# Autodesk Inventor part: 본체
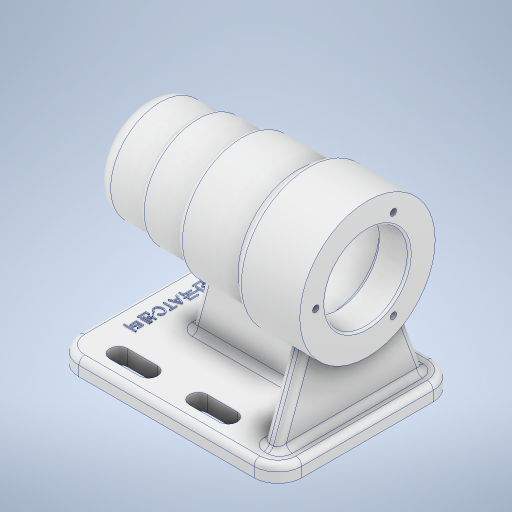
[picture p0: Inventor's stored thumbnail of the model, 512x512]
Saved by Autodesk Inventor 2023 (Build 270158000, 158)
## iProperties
Created: 2022-07
Part Number: 본체
Material: 알루미늄 6061
Document SubType Name: Modeling
Designer: owner
Density: 2.7 g/cm^3
Appearance: 알루미늄 - 평지
Mass: 695.124 g
Surface Area: 704.983 cm^2
Volume: 257.453 cm^3
Author: owner
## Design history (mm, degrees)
sketch "스케치1"
  geometry: L1 (44, -45)-(-44, -45); L2 (-56, -33)-(-56, 33); L3 (-44, 45)-(44, 45); L4 (56, 33)-(56, -33); L5 (56, -45)-(-56, 45); L6 (-56, -45)-(56, 45); A1 r 12 centre (44, -33) between (44, -45) and (56, -33); A2 r 12 centre (44, 33) between (56, 33) and (44, 45); A3 r 12 centre (-44, 33) between (-44, 45) and (-56, 33); A4 r 12 centre (-44, -33) between (-56, -33) and (-44, -45); 1 further point
  constraints: 12 end point, 8 point on circle, 8 point on line, 8 tangent, 4 centre point, 3 equal radius, 2 midpoint, 2 parallel, 1 horizontal, 1 perpendicular
  dimensions: "d0" = 112 distance of L5.end L6.end; "d1" = 90 distance of L6.start L5.end; "d2" = 12 radius of A1
extrude "돌출1" new body sketch "스케치1" distance "d3" = 8; taper "d4" = 0 deg
sketch "스케치2"
  geometry: L1 (-36, 33)-(-21, 33); L2 (-36, 28.5)-(-21, 28.5); L3 (-21, 37.5)-(-36, 37.5); L4 (4, 33)-(19, 33); L5 (4, 28.5)-(19, 28.5); L6 (19, 37.5)-(4, 37.5); L7 (56, -33)-(56, 33) reference; L8 (-56, 33)-(-56, -33) reference; L9 (-56, 33)-(-56, -33) reference; L10 (-56, 0)-(56, 0); L11 (-21, -37.5)-(-36, -37.5); L12 (-36, -28.5)-(-21, -28.5); L13 (19, -37.5)-(4, -37.5); L14 (4, -28.5)-(19, -28.5); A1 r 4.5 centre (-36, 33) between (-36, 37.5) and (-36, 28.5); A2 r 4.5 centre (-21, 33) between (-21, 28.5) and (-21, 37.5); A3 r 4.5 centre (4, 33) between (4, 37.5) and (4, 28.5); A4 r 4.5 centre (19, 33) between (19, 28.5) and (19, 37.5); A5 r 4.5 centre (-21, -33) between (-21, -37.5) and (-21, -28.5); A6 r 4.5 centre (-36, -33) between (-36, -28.5) and (-36, -37.5); A7 r 4.5 centre (4, -33) between (4, -28.5) and (4, -37.5); A8 r 4.5 centre (19, -33) between (19, -37.5) and (19, -28.5); 3 further points
  constraints: 26 end point, 16 point on circle, 12 symmetric about line, 8 centre point, 8 tangent, 4 midpoint, 2 horizontal, 2 parallel, 4 other
  dimensions: "d5" = 15 distance of L1.start L1.end; "d6" = 9 diameter of A2; "d7" = 15 distance of L4.start L4.end; "d8" = 9 diameter of A4; "d10" = 33 vertical distance of point (0, 0) point (-28.5, 33); "d11" = 33 vertical distance of point (0, 0) point (11.5, 33); "d12" = 25 distance of L4.start L1.end; "d13" = 20 distance from line of L8 L1.start
extrude "돌출2" cut sketch "스케치2" extent not by distance; stored distance "d14" = 0; taper "d15" = 0 deg
sketch "스케치3"
  geometry: L1 (-56, 70)-(56, 70); L2 (-44, 0)-(44, 0) reference; L3 (56, 70)-(56, 104); L4 (56, 104)-(24, 104); L5 (24, 104)-(24, 100); L6 (24, 100)-(-10, 100); L7 (-10, 100)-(-10, 97); L8 (-10, 97)-(-32, 97); L9 (-32, 97)-(-32, 95); L10 (-32, 95)-(-56, 95); L11 (-56, 95)-(-56, 70); L12 (56, 91)-(41, 91); L13 (41, 91)-(41, 91); L14 (38, 94)-(-10, 94); L15 (-13, 91)-(-13, 91); L16 (-13, 91)-(-24.7, 91); L17 (-25, 90.7)-(-25, 87.5); L18 (-25, 87.5)-(-42.7, 87.5); L19 (-43, 87.2)-(-43, 86); L20 (-43, 86)-(-46.7, 86); L21 (-47, 85.7)-(-47, 80.5); L22 (-47, 80.5)-(-47, 80.5); L23 (-50, 77.5)-(-50, 70); A1 r 3 centre (-47, 77.5) between (-47, 80.5) and (-50, 77.5); A2 r 0.3 centre (-46.7, 85.7) between (-46.7, 86) and (-47, 85.7); A3 r 0.3 centre (-42.7, 87.2) between (-42.7, 87.5) and (-43, 87.2); A4 r 3 centre (-10, 91) between (-10, 94) and (-13, 91); A5 r 3 centre (38, 91) between (41, 91) and (38, 94); A6 r 0.3 centre (-24.7, 90.7) between (-24.7, 91) and (-25, 90.7); 6 further points
  constraints: 44 end point, 18 perpendicular, 12 point on circle, 12 tangent, 6 centre point, 2 equal radius, 2 horizontal, 2 point on line, 2 vertical, 2 vertical alignment
  dimensions: "d16" = 70 distance between parallel lines of L2 L1; "d17" = 80 distance between parallel lines of L11 L5; "d18" = 46 distance between parallel lines of L11 L7; "d19" = 24 distance between parallel lines of L11 L9; "d20" = 68 diameter of L4 L1; "d21" = 60 diameter of L6 L1; "d22" = 54 diameter of L8 L1; "d23" = 50 diameter of L10 L1; "d24" = 21 diameter of L22 L1; "d25" = 32 diameter of L20 L1; "d26" = 35 diameter of L18 L1; "d27" = 42 diameter of L16 L1; "d28" = 48 diameter of L14 L1; "d29" = 42 diameter of L12 L1; "d30" = 18 distance between parallel lines of L17 L19; "d31" = 12 distance between parallel lines of L15 L17; "d32" = 54 distance between parallel lines of L13 L15; "d33" = 15 distance between parallel lines of L3 L13; "d35" = 4 distance between parallel lines of L19 L21; "d36" = 3 distance between parallel lines of L21 L23; "d37" = 3 radius of A1; "d38" = 0.3 radius of A2; "d39" = 3 radius of A4; "d40" = 0.3 radius of A6
revolve "회전1" sketch "스케치3" stored, may be unused: angle "d41" = 90 deg
fillet "모깎기1" dims "d42" = 1
fillet "모깎기3" dims "d44" = 3
sketch "스케치4" dims "d52" = 52
  geometry: C1 r 34 at (0, 0) reference; C2 r 10.5 at (0, 0) reference; C3 r 7.5 at (0, 0) reference; 4 further points
  constraints: 3 horizontal alignment, 1 coincident, 2 other
hole "구멍1" sketch "스케치4" at (-26, 0) diameter "d45" = 3.242; stored, may be unused: countersink angle "d49" = 90 deg, drill point angle "d51" = 118 deg; dims "d46" = 8, "d47" = 4, "d48" = 2, "d50" = 11
node "작업 평면1"
sketch "스케치6"
  geometry: L1 (9.591, 45.342)-(-4, 8); L2 (0, 8)-(66, 8) reference; L3 (-12, 0)-(-12, 8) reference; L4 (33, 0)-(33, 70); L5 (56.409, 45.342)-(70, 8); L6 (61.5, 8)-(70.5, 8) reference; L7 (70.5, 8)-(-4, 8); 2 further points
  constraints: 8 end point, 2 symmetric about line, 1 collinear, 1 point on line, 1 vertical, 2 other
  dimensions: "d66" = 110 deg angle of L2 L1; "d67" = 8 distance from line of L3 L1.end
extrude "돌출4" join sketch "스케치6" distance "d68" = 8; taper "d69" = 0 deg
sketch "스케치7"
  geometry: L1 (-29.172, 43)-(-10, 43) reference; L2 (-19.622, 43)-(-29, 8); L3 (44, 8)-(-44, 8) reference; L4 (56, 0)-(56, 8) reference; L5 (48, 51.6)-(48, -8.6) reference; 1 further point
  constraints: 2 end point, 2 point on line
  dimensions: "d70" = 105 deg angle of L3 L2; "d72" = 77 distance from line of L5 L2.end
feature "리브1" sketch "스케치7" dims "d73" = 1, "d74" = 8, "d75" = 0, "d76" = 0, "d77" = 1, "d78" = 1
fillet "모깎기4" dims "d79" = 3
fillet "모깎기5" dims "d80" = 3
fillet "모깎기6" dims "d81" = 3
sketch "스케치8"
  geometry: L1 (-56, 33)-(-56, -33) reference; A1 r 4.5 centre (-36, 33) between (-36, 37.5) and (-36, 28.5) reference; 3 further points
  constraints: 1 point on circle, 1 other
  dimensions: "d82" = 12 distance from line of L1 point (-44, 0); "d83" = 33 vertical distance of point (-44, 0) point (-40.5, 33)
feature "엠보싱1" sketch "스케치8" dims "d0" = 112, "d1" = 90, "d2" = 12, "d84" = 0.5, "d85" = 0
fillet "모깎기7" dims "d86" = 8
node "솔리드1"
pattern_circular "원형 패턴1" dims angle "d56" = 360 deg
feature "A9D066F2-1C7D-4E18-AEED-F7BC21143FA4" dims "d45" = 3.242, "d46" = 8, "d47" = 4, "d48" = 2, "d49" = 90 deg, "d50" = 11, "d51" = 118 deg
other parameters: "d65" = -8
